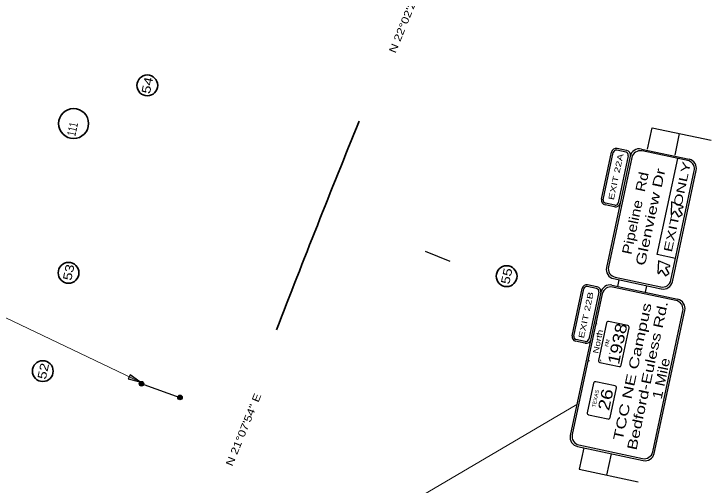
# Model space of a CAD drawing. Extents: x 2363411 to 2369702, y 6977197 to 6988655.
# Drawn here: x 2365218 to 2366344, y 6981687 to 6982449 of the extents above; entities that cross this region are included whole.
import ezdxf
from ezdxf.enums import TextEntityAlignment as Align

# ---------------------------------------------------------------- set-up
doc = ezdxf.new("R2010")
doc.units = 0
doc.header["$LTSCALE"] = 5.6
for name, color, linetype, lineweight in [('1', 7, 'Continuous', 25), ('17', 7, 'Continuous', 35), ('23', 7, 'Continuous', 25), ('37', 7, 'Continuous', 13)]:
    doc.layers.add(name, color=color, linetype=linetype, lineweight=lineweight)
doc.layers.add('28', color=7, linetype='Continuous')

msp = doc.modelspace()

# ---------------------------------------------------------------- hatches: boundary and pattern name
at = {"layer": '1'}
for points in [[(2365420.991, 6981854), (2365405.196, 6981865.495), (2365402.096, 6981858.993)], [(2365426.49, 6981853.45, 1), (2365421.059, 6981848.331, 1)], [(2365488.65, 6981831.372, 1), (2365483.22, 6981826.253, 1)]]:
    msp.add_hatch(color=256, dxfattribs=at).paths.add_polyline_path(points)

# ---------------------------------------------------------------- linework, layer by layer
for p, q in [((2366241.763, 6982230.177), (2366249.192, 6982264.951)), ((2366249.192, 6982264.951), (2366344.444, 6982244.598)), ((2366286.266, 6982220.672), (2366293.696, 6982255.442)), ((2366207.062, 6982225.274), (2366191.945, 6982228.488)), ((2366207.647, 6982228.022), (2366192.531, 6982231.235)), ((2366231.742, 6982230.513), (2366309.274, 6982213.945)), ((2366308.808, 6982211.153), (2366232.996, 6982227.356)), ((2366167.413, 6982149.157), (2366183.636, 6982225.461)), ((2366170.162, 6982148.572), (2366186.383, 6982224.875)), ((2366213.892, 6982218.948), (2366175.391, 6982038.762)), ((2366216.253, 6982216.519), (2366178.532, 6982040.016)), ((2366210.674, 6982219.713), (2366194.443, 6982143.41)), ((2366257.501, 6982059.981), (2366290.632, 6982215.037)), ((2366279.649, 6982018.411), (2366317.405, 6982195.096)), ((2366281.953, 6982015.685), (2366320.447, 6982195.863)), ((2366188.297, 6982137.05), (2366173.189, 6982140.263)), ((2366188.884, 6982139.799), (2366173.773, 6982143.011)), ((2366280.714, 6982144.881), (2366279.961, 6982125.72)), ((2366298.486, 6982137.717), (2366280.714, 6982144.881)), ((2366281.782, 6982125.016), (2366285.116, 6982129.438)), ((2366292.975, 6982134.527), (2366298.383, 6982135.783)), ((2366287.178, 6982053.64), (2366257.501, 6982059.981)), ((2366259.378, 6982049.53), (2366258.625, 6982030.369)), ((2366277.15, 6982042.366), (2366259.378, 6982049.53)), ((2366271.639, 6982039.176), (2366277.047, 6982040.432)), ((2366271.639, 6982039.176), (2366277.047, 6982040.432)), ((2366260.446, 6982029.665), (2366263.78, 6982034.087)), ((2366260.446, 6982029.665), (2366263.78, 6982034.087)), ((2366186.957, 6982020.897), (2366263.873, 6982004.46)), ((2366189.393, 6982023.267), (2366263.288, 6982007.475)), ((2366193.777, 6982008.284), (2366196.056, 6982018.953)), ((2366119.723, 6981928.626), (2366135.946, 6982004.93)), ((2366122.472, 6981928.041), (2366138.693, 6982004.344)), ((2366159.372, 6982004.743), (2366144.255, 6982007.957)), ((2366159.957, 6982007.491), (2366144.841, 6982010.704)), ((2366184.125, 6982010.347), (2366290.791, 6981987.558)), ((2366290.327, 6981984.765), (2366185.379, 6982007.19)), ((2366238.281, 6981998.776), (2366240.56, 6982009.444)), ((2366166.271, 6981998.779), (2366116.835, 6981767.404)), ((2366168.637, 6981996.35), (2366119.988, 6981768.654)), ((2366162.984, 6981999.182), (2366146.753, 6981922.879)), ((2366250.229, 6981740.826), (2366298.918, 6981968.705)), ((2366252.528, 6981738.097), (2366301.964, 6981969.472)), ((2366175.303, 6981949.331), (2366162.406, 6981888.651)), ((2366209.876, 6981944.852), (2366178.644, 6981951.493)), ((2366199.14, 6981880.837), (2366212.037, 6981941.518)), ((2366140.607, 6981916.519), (2366125.499, 6981919.732)), ((2366141.194, 6981919.268), (2366126.083, 6981922.48)), ((2366164.569, 6981885.317), (2366195.8, 6981878.674)), ((2365427.361, 6981849.858), (2365485.94, 6981828.805)), ((2366154.622, 6981852.061), (2366144.38, 6981803.909)), ((2366189.194, 6981847.589), (2366157.963, 6981854.232)), ((2366181.114, 6981796.097), (2366191.356, 6981844.248)), ((2366146.551, 6981800.57), (2366177.781, 6981793.933)), ((2366128.402, 6981749.537), (2366234.735, 6981726.825)), ((2366130.838, 6981751.907), (2366233.485, 6981729.977)), ((2366138.599, 6981747.359), (2366131.168, 6981712.586)), ((2366183.1, 6981737.847), (2366175.672, 6981703.076)), ((2366131.168, 6981712.586), (2366226.42, 6981692.234))]:
    msp.add_line(p, q, dxfattribs=at)
at = {"layer": '1', "lineweight": 13}
msp.add_line((2365420.991, 6981854), (2364852.9, 6982125.825), dxfattribs=at)
at = {"layer": '1'}
for points in [[(2366286.234, 6982129.399), (2366291.879, 6982120.675), (2366295.051, 6982122.734), (2366298.218, 6982124.786), (2366292.573, 6982133.499)], [(2366277.15, 6982042.366), (2366259.378, 6982049.53), (2366258.625, 6982030.369)], [(2366264.898, 6982034.048), (2366270.543, 6982025.324), (2366273.715, 6982027.383), (2366276.882, 6982029.435), (2366271.237, 6982038.148)], [(2366264.898, 6982034.048), (2366270.543, 6982025.324), (2366273.715, 6982027.383), (2366276.882, 6982029.435), (2366271.237, 6982038.148)]]:
    msp.add_lwpolyline(points, dxfattribs=at)
msp.add_lwpolyline([(2365420.991, 6981854), (2365405.196, 6981865.495), (2365402.096, 6981858.993)], close=True, dxfattribs=at)
at = {"layer": '1', "lineweight": 13}
msp.add_lwpolyline([(2365607.98, 6981522.117), (2365840.659, 6981648.883), (2366127.574, 6981817.426)], dxfattribs=at)
at = {"layer": '1'}
for centre in [(2365423.775, 6981850.891), (2365485.935, 6981828.812)]:
    msp.add_circle(centre, 3.732, dxfattribs=at)
at = {"layer": '1', "lineweight": 35}
msp.add_arc((2387019.104, 6973675.721), 22918.312, 157.9611, 158.86822, dxfattribs=at)
at = {"layer": '1'}
for centre, radius, start, end in [((2366190.973, 6982223.899), 7.501, 77.99433, 167.99433), ((2366190.973, 6982223.899), 4.688, 77.99433, 167.99433), ((2366206.625, 6982220.87), 7.501, 347.99433, 77.99433), ((2366228.604, 6982215.8), 15.049, 77.93925, 169.35675), ((2366230.051, 6982213.568), 14.108, 77.93925, 167.93925), ((2366206.087, 6982220.685), 4.688, 347.99433, 77.99433), ((2366303.604, 6982198.044), 14.108, 347.93925, 68.3439), ((2366305.797, 6982199.307), 15.049, 346.76968, 76.63979), ((2366174.747, 6982147.598), 7.501, 167.99433, 257.99433), ((2366174.747, 6982147.598), 4.688, 167.99433, 257.99433), ((2366190.33, 6982144.285), 7.501, 257.99433, 347.99433), ((2366189.861, 6982144.384), 4.688, 257.99433, 347.99433), ((2366298.134, 6982136.765), 1.012, 282.81961, 68.20075), ((2366280.973, 6982125.646), 1.012, 177.67774, 323.05888), ((2366285.646, 6982129.043), 0.675, 32.93925, 142.92235), ((2366293.124, 6982133.888), 0.675, 102.95614, 212.93925), ((2366190.107, 6982035.619), 15.049, 167.93925, 257.93925), ((2366192.34, 6982037.066), 14.108, 167.93925, 257.93925), ((2366271.789, 6982038.537), 0.675, 102.95614, 212.93925), ((2366271.789, 6982038.537), 0.675, 102.95614, 212.93925), ((2366276.799, 6982041.414), 1.012, 282.81961, 68.20075), ((2366276.799, 6982041.414), 1.012, 282.81961, 68.20075), ((2366259.637, 6982030.295), 1.012, 177.67774, 323.05888), ((2366259.637, 6982030.295), 1.012, 177.67774, 323.05888), ((2366264.311, 6982033.692), 0.675, 32.93925, 142.92235), ((2366264.311, 6982033.692), 0.675, 32.93925, 142.92235), ((2366265.854, 6982021.358), 14.108, 257.93925, 347.93925), ((2366267.3, 6982019.126), 15.049, 257.93925, 346.76968), ((2366143.284, 6982003.368), 7.501, 77.99433, 167.99433), ((2366143.284, 6982003.368), 4.688, 77.99433, 167.99433), ((2366158.397, 6982000.154), 4.688, 347.99433, 77.99433), ((2366158.935, 6982000.339), 7.501, 347.99433, 77.99433), ((2366180.987, 6981995.634), 15.049, 77.93925, 169.35675), ((2366182.434, 6981993.402), 14.108, 77.93925, 167.93925), ((2366285.121, 6981971.652), 14.108, 347.93925, 68.3439), ((2366287.315, 6981972.916), 15.049, 346.76968, 76.63979), ((2366178.056, 6981948.743), 2.813, 77.99516, 167.99516), ((2366209.29, 6981942.101), 2.813, 347.99516, 77.99516), ((2366127.057, 6981927.067), 7.501, 167.99433, 257.99433), ((2366127.057, 6981927.067), 4.688, 167.99433, 257.99433), ((2366142.171, 6981923.853), 4.688, 257.99433, 347.99433), ((2366142.64, 6981923.753), 7.501, 257.99433, 347.99433), ((2366165.151, 6981888.066), 2.813, 167.99516, 257.99516), ((2366196.385, 6981881.425), 2.813, 257.99516, 347.99516), ((2366157.372, 6981851.482), 2.813, 77.99516, 167.99516), ((2366188.607, 6981844.84), 2.813, 347.99516, 77.99516), ((2366147.131, 6981803.319), 2.813, 167.99516, 257.99516), ((2366178.365, 6981796.677), 2.813, 257.99516, 347.99516), ((2366131.552, 6981764.259), 15.049, 167.93925, 257.93925), ((2366133.785, 6981765.706), 14.108, 167.93925, 257.93925), ((2366236.433, 6981743.773), 14.108, 257.93925, 347.93925), ((2366237.879, 6981741.54), 15.049, 257.93925, 346.76968)]:
    msp.add_arc(centre, radius, start, end, dxfattribs=at)
at = {"layer": '17'}
for centre, radius in [((2365433.096, 6982333.369), 16.828), ((2365313.995, 6982271.665), 24.19), ((2365305.772, 6982030.262), 16.828), ((2366013.962, 6982024.898), 16.828), ((2365264.089, 6981871.372), 16.828)]:
    msp.add_circle(centre, radius, dxfattribs=at)
at = {"layer": '23'}
msp.add_line((2365882.454, 6982065.378), (2365921.973, 6982049.25), dxfattribs=at)
at = {"layer": '37'}
for p, q in [((2366195.734, 6982137.309), (2366196.979, 6982138.881)), ((2366159.436, 6981949.258), (2366159.844, 6981947.292)), ((2366161.92, 6981932.314), (2366161.027, 6981930.525)), ((2366148.044, 6981916.778), (2366149.289, 6981918.35)), ((2366175.825, 6981918.255), (2366174.206, 6981917.09)), ((2366181.599, 6981899.949), (2366179.684, 6981900.501)), ((2366166.357, 6981887.484), (2366165.58, 6981889.326)), ((2366146.732, 6981886.857), (2366147.204, 6981888.791))]:
    msp.add_line(p, q, dxfattribs=at)

# ---------------------------------------------------------------- texts
at = {"layer": '1'}
for s, height, rotation, width, p in [('EXIT 22A', 9.188, 77.994, 1.45, (2366195.088, 6982184.656)), ('EXIT  ONLY', 13.5, 77.939, 1.5, (2366296.401, 6982135.676)), ('Pipeline  Rd', 15.68, 77.939, 1.2, (2366229.676, 6982125.226)), ('Glenview Dr', 15.68, 77.939, 1.4, (2366254.083, 6982118.937)), ('EXIT 22B', 9.188, 77.994, 1.45, (2366146.744, 6981961.059)), ('TCC NE Campus', 15.68, 77.939, 1.4, (2366224.941, 6981868.887)), ('Bedford-Euless Rd.', 15.68, 77.939, 1.35, (2366249.347, 6981862.599)), ('North', 9.188, 77.994, 1.3, (2366166.07, 6981918.215)), ('1 Mile', 15.68, 77.939, 1.2, (2366271.433, 6981857.88))]:
    msp.add_text(s, height=height, rotation=rotation, dxfattribs=dict(at, width=width)).set_placement(p, align=Align.CENTER)
for s, height, width, p in [('1938', 18.75, 1.2, (2366195.403, 6981881.108)), ('TEXAS', 6, 1.1, (2366157.494, 6981812.201)), ('26', 18.75, 1.25, (2366179.504, 6981806.331))]:
    msp.add_text(s, height=height, rotation=77.995, dxfattribs=dict(at, width=width)).set_placement(p)
msp.add_text('FM', height=6, rotation=77.995, dxfattribs=at).set_placement((2366178.339, 6981910.24))
at = {"layer": '17'}
for s, width, p in [('54', 1.3, (2365439.96, 6982331.992)), ('111', 0.7, (2365318.983, 6982261.219)), ('53', 1.25, (2365312.795, 6982029.629)), ('55', 1.25, (2366020.844, 6982023.61)), ('52', 1.25, (2365271.695, 6981869.836))]:
    msp.add_text(s, height=14, rotation=77.939, dxfattribs=dict(at, width=width)).set_placement(p, align=Align.CENTER)
at = {"layer": '28', "width": 1.25}
for s, p in [('N 22°02\'20" E', (2365857.86, 6982442.388)), ('N 21°07\'54" E', (2365594.069, 6981774.394))]:
    msp.add_text(s, height=12, rotation=67.836, dxfattribs=at).set_placement(p, align=Align.CENTER)

doc.saveas('drawing.dxf')
